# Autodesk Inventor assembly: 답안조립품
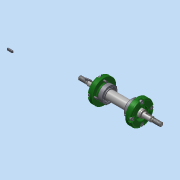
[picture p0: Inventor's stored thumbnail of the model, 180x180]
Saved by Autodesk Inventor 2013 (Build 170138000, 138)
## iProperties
Created: 2015-11
Part Number: 답안조립품
Document SubType Name: Assembly
Designer: ST1
Author: ST1
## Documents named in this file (7)
- C:\Users\ST1\Desktop\451109V1027\답안조립품.iam
- C:\Users\ST1\Desktop\451109V1027\1-본체.ipt
- C:\Users\ST1\Desktop\451109V1027\커버.ipt
- C:\Users\ST1\Desktop\451109V1027\축.ipt
- C:\Users\ST1\Desktop\451109V1027\키 3 x 3 x 12.ipt
- C:\Users\ST1\Desktop\451109V1027\베어링 15 x 32 x 9.ipt
- C:\Users\ST1\Desktop\451109V1027\볼트 M4 x 12.ipt
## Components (11 placed, 3 different names)
1. 1-본체:1
2. KS B 2023 6002 - 15 x 32 x 9:1
3. KS B 2023 6002 - 15 x 32 x 9:2
4. ISO 4762 M4 x 12:2
5. ISO 4762 M4 x 12:3
6. ISO 4762 M4 x 12:4
7. ISO 4762 M4 x 12:5
8. ISO 4762 M4 x 12:6
9. ISO 4762 M4 x 12:7
10. ISO 4762 M4 x 12:8
11. ISO 4762 M4 x 12:9
